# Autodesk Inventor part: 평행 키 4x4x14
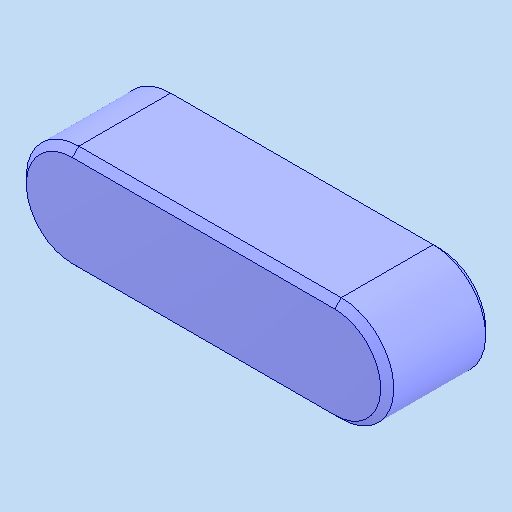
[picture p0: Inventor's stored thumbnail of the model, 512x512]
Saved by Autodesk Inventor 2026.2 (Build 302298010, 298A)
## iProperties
Created: 2026-03
Part Number: 평행 키 4x4x14
Material: 강철, 연강
Description: 키 및 해당 키홈
Document SubType Name: Modeling
Designer: PC-2-06
Density: 7.85 g/cm^3
Appearance: 기본값
Author: jhkim
Sending System: Autodesk Inventor 2026
Preprocessor: ST-DEVELOPER v20.1
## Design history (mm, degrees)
feature "Solid1"
node "솔리드1"
